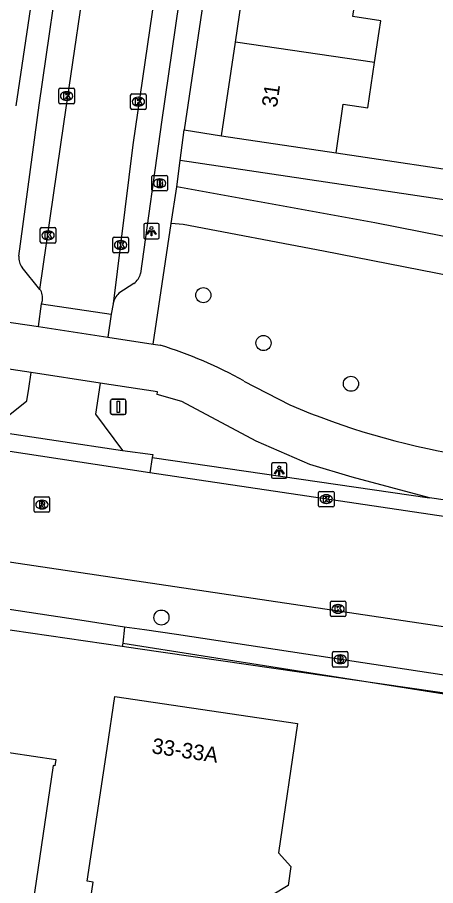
# Model space of a CAD drawing. Extents: x 163686 to 164493, y 382719 to 383870.
# Drawn here: x 164082.8 to 164109.8, y 382884.7 to 382940.9 of the extents above; entities that cross this region are included whole.
import ezdxf

# ---------------------------------------------------------------- set-up
doc = ezdxf.new("R2010")
doc.units = 0
for name, color, linetype in [('IMGEO_Boom', 7, 'Continuous'), ('IMGEO_Brandkraan', 7, 'Continuous'), ('IMGEO_Fietspad_gesloten', 7, 'Continuous'), ('IMGEO_Groenvoorziening', 7, 'Continuous'), ('IMGEO_Hek', 7, 'Continuous'), ('IMGEO_Kolk', 7, 'Continuous'), ('IMGEO_Lichtpunt', 7, 'Continuous'), ('IMGEO_Pand', 7, 'Continuous'), ('IMGEO_Pand_nummerreeks', 7, 'Continuous'), ('IMGEO_Rijbaan_lokaal_gesloten', 7, 'Continuous'), ('IMGEO_Rijbaan_lokaal_open', 7, 'Continuous'), ('IMGEO_Rioolput', 7, 'Continuous'), ('IMGEO_Verkeersbordpaal', 7, 'Continuous'), ('IMGEO_Voetpad_open', 7, 'Continuous')]:
    doc.layers.add(name, color=color, linetype=linetype)

msp = doc.modelspace()

# ---------------------------------------------------------------- linework, layer by layer
at = {"layer": 'IMGEO_Boom'}
for centre in [(164094.797, 382922.922), (164098.694, 382919.82), (164104.362, 382917.184), (164092.085, 382902.04)]:
    msp.add_circle(centre, 0.489, dxfattribs=at)
at = {"layer": 'IMGEO_Brandkraan'}
for p, q in [((164091.469, 382929.744), (164091.469, 382930.596)), ((164091.544, 382930.67), (164092.396, 382930.67)), ((164092.47, 382930.596), (164092.47, 382929.744)), ((164091.957, 382930.45), (164091.982, 382930.45)), ((164092.396, 382929.67), (164091.544, 382929.67)), ((164091.98, 382929.89), (164091.955, 382929.89)), ((164103.167, 382898.911), (164103.167, 382899.763)), ((164103.242, 382899.837), (164104.094, 382899.837)), ((164103.655, 382899.617), (164103.68, 382899.617)), ((164104.168, 382899.763), (164104.168, 382898.911)), ((164103.678, 382899.057), (164103.653, 382899.057)), ((164104.094, 382898.837), (164103.242, 382898.837))]:
    msp.add_line(p, q, dxfattribs=at)
for points in [[(164091.469, 382929.744), (164091.469, 382930.596)], [(164091.544, 382930.67), (164092.396, 382930.67)], [(164092.47, 382930.596), (164092.47, 382929.744)], [(164091.817, 382930.37), (164091.817, 382929.97), (164092.03, 382929.97)], [(164092.048, 382930.37), (164091.817, 382930.37)], [(164091.996, 382930.289), (164091.942, 382930.289), (164091.942, 382930.213)], [(164091.942, 382930.213), (164091.995, 382930.213)], [(164092.004, 382930.137), (164091.942, 382930.137), (164091.942, 382930.056)], [(164091.942, 382930.056), (164092.004, 382930.056)], [(164092.396, 382929.67), (164091.544, 382929.67)], [(164103.167, 382898.911), (164103.167, 382899.763)], [(164103.242, 382899.837), (164104.094, 382899.837)], [(164103.515, 382899.537), (164103.515, 382899.137), (164103.728, 382899.137)], [(164103.746, 382899.537), (164103.515, 382899.537)], [(164104.168, 382899.763), (164104.168, 382898.911)], [(164103.694, 382899.456), (164103.64, 382899.456), (164103.64, 382899.38)], [(164103.64, 382899.38), (164103.693, 382899.38)], [(164103.702, 382899.304), (164103.64, 382899.304), (164103.64, 382899.223)], [(164103.64, 382899.223), (164103.702, 382899.223)], [(164104.094, 382898.837), (164103.242, 382898.837)]]:
    msp.add_lwpolyline(points, dxfattribs=at)
for centre, radius, start, end in [((164091.546, 382930.594), 0.0765, 91.552, 178.448), ((164091.546, 382930.594), 0.0765, 91.552, 178.448), ((164092.394, 382930.594), 0.0765, 1.552, 88.448), ((164092.394, 382930.594), 0.0765, 1.552, 88.448), ((164091.997, 382930.251), 0.0379, 267.8285, 90.9355), ((164092.005, 382930.096), 0.0404, 269.8759, 90.5077), ((164092.036, 382930.221), 0.251, 268.6676, 293.5347), ((164092.052, 382930.225), 0.145, 59.4692, 91.5367), ((164092.077, 382930.272), 0.0922, 285.5137, 58.1501), ((164092.082, 382930.08), 0.105, 301.3115, 78.989), ((164091.546, 382929.746), 0.0765, 181.552, 268.448), ((164091.546, 382929.746), 0.0765, 181.552, 268.448), ((164092.394, 382929.746), 0.0765, 271.552, 358.448), ((164092.394, 382929.746), 0.0765, 271.552, 358.448), ((164103.244, 382899.761), 0.0765, 91.552, 178.448), ((164103.244, 382899.761), 0.0765, 91.552, 178.448), ((164103.75, 382899.392), 0.145, 59.4692, 91.5367), ((164104.092, 382899.761), 0.0765, 1.552, 88.448), ((164104.092, 382899.761), 0.0765, 1.552, 88.448), ((164103.695, 382899.418), 0.0379, 267.8285, 90.9355), ((164103.703, 382899.263), 0.0404, 269.8759, 90.5077), ((164103.734, 382899.388), 0.251, 268.6676, 293.5347), ((164103.775, 382899.439), 0.0922, 285.5137, 58.1501), ((164103.78, 382899.247), 0.105, 301.3115, 78.989), ((164103.244, 382898.913), 0.0765, 181.552, 268.448), ((164103.244, 382898.913), 0.0765, 181.552, 268.448), ((164104.092, 382898.913), 0.0765, 271.552, 358.448), ((164104.092, 382898.913), 0.0765, 271.552, 358.448)]:
    msp.add_arc(centre, radius, start, end, dxfattribs=at)
for centre, major_axis, ratio, start_param, end_param in [((164091.956, 382930.17), (-0.387, 0.002), 0.722429, 4.712389, 7.853982), ((164091.981, 382930.17), (-0.39, 0.002), 0.717154, 1.570796, 4.712389), ((164103.654, 382899.337), (-0.387, 0.002), 0.722429, 4.712389, 7.853982), ((164103.679, 382899.337), (-0.39, 0.002), 0.717154, 1.570796, 4.712389)]:
    msp.add_ellipse(centre, major_axis=major_axis, ratio=ratio, start_param=start_param, end_param=end_param, dxfattribs=at)
at = {"layer": 'IMGEO_Fietspad_gesloten'}
for points in [[(164080.709, 382921.39), (164084.114, 382920.888)], [(164088.61, 382920.207), (164091.557, 382919.741)], [(164091.557, 382919.741), (164092.007, 382919.674)], [(164083.648, 382917.908), (164080.015, 382918.445), (164079.969, 382918.239)], [(164109.452, 382909.801), (164104.433, 382911.123), (164101.705, 382911.946), (164098.222, 382913.466), (164093.404, 382916.027), (164091.798, 382916.497), (164091.819, 382916.666), (164088.11, 382917.218)], [(164097.423, 382917.361), (164100.411, 382915.813)], [(164122.324, 382907.915), (164109.452, 382909.801)]]:
    msp.add_lwpolyline(points, dxfattribs=at)
for centre, radius, start, end in [((164084.043, 382893.528), 27.333, 60.6896, 73.0589), ((164119.389, 382960.225), 48.297, 246.8617, 260.5241)]:
    msp.add_arc(centre, radius, start, end, dxfattribs=at)
at = {"layer": 'IMGEO_Groenvoorziening'}
for points in [[(164093.559, 382933.622), (164095.981, 382933.235)], [(164139.939, 382924.7), (164093.297, 382931.638)], [(164103.402, 382932.145), (164113.229, 382930.665)]]:
    msp.add_lwpolyline(points, dxfattribs=at)
at = {"layer": 'IMGEO_Hek'}
msp.add_lwpolyline([(164089.574, 382900.373), (164110.403, 382897.109), (164139.681, 382892.918)], dxfattribs=at)
at = {"layer": 'IMGEO_Kolk'}
for p, q in [((164085.442, 382935.392), (164085.442, 382936.244)), ((164085.517, 382936.318), (164086.369, 382936.318)), ((164085.93, 382936.098), (164085.955, 382936.098)), ((164086.443, 382936.244), (164086.443, 382935.392)), ((164085.953, 382935.538), (164085.928, 382935.538)), ((164090.09, 382935.03), (164090.09, 382935.882)), ((164090.165, 382935.956), (164091.017, 382935.956)), ((164090.578, 382935.736), (164090.603, 382935.736)), ((164091.091, 382935.882), (164091.091, 382935.03)), ((164086.369, 382935.318), (164085.517, 382935.318)), ((164090.601, 382935.176), (164090.576, 382935.176)), ((164091.017, 382934.956), (164090.165, 382934.956)), ((164084.238, 382926.368), (164084.238, 382927.22)), ((164084.313, 382927.294), (164085.165, 382927.294)), ((164085.239, 382927.22), (164085.239, 382926.368)), ((164084.726, 382927.074), (164084.751, 382927.074)), ((164088.941, 382925.747), (164088.941, 382926.599)), ((164089.016, 382926.673), (164089.868, 382926.673)), ((164089.942, 382926.599), (164089.942, 382925.747)), ((164085.165, 382926.294), (164084.313, 382926.294)), ((164084.749, 382926.514), (164084.724, 382926.514)), ((164089.429, 382926.453), (164089.454, 382926.453)), ((164089.868, 382925.673), (164089.016, 382925.673)), ((164089.452, 382925.893), (164089.427, 382925.893)), ((164102.265, 382909.284), (164102.265, 382910.136)), ((164102.34, 382910.21), (164103.192, 382910.21)), ((164102.753, 382909.99), (164102.778, 382909.99)), ((164103.266, 382910.136), (164103.266, 382909.284)), ((164103.192, 382909.21), (164102.34, 382909.21)), ((164102.776, 382909.43), (164102.751, 382909.43)), ((164103.027, 382902.175), (164103.027, 382903.027)), ((164103.102, 382903.101), (164103.954, 382903.101)), ((164104.028, 382903.027), (164104.028, 382902.175)), ((164103.515, 382902.881), (164103.54, 382902.881)), ((164103.954, 382902.101), (164103.102, 382902.101)), ((164103.538, 382902.321), (164103.513, 382902.321))]:
    msp.add_line(p, q, dxfattribs=at)
for points in [[(164085.442, 382935.392), (164085.442, 382936.244)], [(164085.517, 382936.318), (164086.369, 382936.318)], [(164086.443, 382936.244), (164086.443, 382935.392)], [(164085.763, 382936.018), (164085.886, 382936.018), (164085.886, 382935.867), (164086.016, 382936.018), (164086.18, 382936.018), (164086.034, 382935.867), (164086.187, 382935.618), (164086.035, 382935.618), (164085.95, 382935.782), (164085.886, 382935.715), (164085.886, 382935.618), (164085.763, 382935.618), (164085.763, 382936.018)], [(164090.09, 382935.03), (164090.09, 382935.882)], [(164090.165, 382935.956), (164091.017, 382935.956)], [(164090.411, 382935.656), (164090.534, 382935.656), (164090.534, 382935.505), (164090.664, 382935.656), (164090.828, 382935.656), (164090.682, 382935.505), (164090.835, 382935.256), (164090.683, 382935.256), (164090.598, 382935.42), (164090.534, 382935.353), (164090.534, 382935.256), (164090.411, 382935.256), (164090.411, 382935.656)], [(164091.091, 382935.882), (164091.091, 382935.03)], [(164086.369, 382935.318), (164085.517, 382935.318)], [(164091.017, 382934.956), (164090.165, 382934.956)], [(164084.238, 382926.368), (164084.238, 382927.22)], [(164084.313, 382927.294), (164085.165, 382927.294)], [(164085.239, 382927.22), (164085.239, 382926.368)], [(164084.559, 382926.994), (164084.682, 382926.994), (164084.682, 382926.843), (164084.812, 382926.994), (164084.976, 382926.994), (164084.83, 382926.843), (164084.983, 382926.594), (164084.831, 382926.594), (164084.746, 382926.758), (164084.682, 382926.691), (164084.682, 382926.594), (164084.559, 382926.594), (164084.559, 382926.994)], [(164088.941, 382925.747), (164088.941, 382926.599)], [(164089.016, 382926.673), (164089.868, 382926.673)], [(164089.942, 382926.599), (164089.942, 382925.747)], [(164085.165, 382926.294), (164084.313, 382926.294)], [(164089.262, 382926.373), (164089.385, 382926.373), (164089.385, 382926.222), (164089.515, 382926.373), (164089.679, 382926.373), (164089.533, 382926.222), (164089.686, 382925.973), (164089.534, 382925.973), (164089.449, 382926.137), (164089.385, 382926.07), (164089.385, 382925.973), (164089.262, 382925.973), (164089.262, 382926.373)], [(164089.868, 382925.673), (164089.016, 382925.673)], [(164102.265, 382909.284), (164102.265, 382910.136)], [(164102.34, 382910.21), (164103.192, 382910.21)], [(164102.586, 382909.91), (164102.709, 382909.91), (164102.709, 382909.759), (164102.839, 382909.91), (164103.003, 382909.91), (164102.857, 382909.759), (164103.01, 382909.51), (164102.858, 382909.51), (164102.773, 382909.674), (164102.709, 382909.607), (164102.709, 382909.51), (164102.586, 382909.51), (164102.586, 382909.91)], [(164103.266, 382910.136), (164103.266, 382909.284)], [(164103.192, 382909.21), (164102.34, 382909.21)], [(164103.027, 382902.175), (164103.027, 382903.027)], [(164103.102, 382903.101), (164103.954, 382903.101)], [(164104.028, 382903.027), (164104.028, 382902.175)], [(164103.348, 382902.801), (164103.471, 382902.801), (164103.471, 382902.65), (164103.601, 382902.801), (164103.765, 382902.801), (164103.619, 382902.65), (164103.772, 382902.401), (164103.62, 382902.401), (164103.535, 382902.565), (164103.471, 382902.498), (164103.471, 382902.401), (164103.348, 382902.401), (164103.348, 382902.801)], [(164103.954, 382902.101), (164103.102, 382902.101)]]:
    msp.add_lwpolyline(points, dxfattribs=at)
for centre, start, end in [((164085.519, 382936.242), 91.552, 178.448), ((164085.519, 382936.242), 91.552, 178.448), ((164086.367, 382936.242), 1.552, 88.448), ((164086.367, 382936.242), 1.552, 88.448), ((164090.167, 382935.88), 91.552, 178.448), ((164090.167, 382935.88), 91.552, 178.448), ((164091.015, 382935.88), 1.552, 88.448), ((164091.015, 382935.88), 1.552, 88.448), ((164085.519, 382935.394), 181.552, 268.448), ((164085.519, 382935.394), 181.552, 268.448), ((164086.367, 382935.394), 271.552, 358.448), ((164086.367, 382935.394), 271.552, 358.448), ((164090.167, 382935.032), 181.552, 268.448), ((164090.167, 382935.032), 181.552, 268.448), ((164091.015, 382935.032), 271.552, 358.448), ((164091.015, 382935.032), 271.552, 358.448), ((164084.315, 382927.218), 91.552, 178.448), ((164084.315, 382927.218), 91.552, 178.448), ((164085.163, 382927.218), 1.552, 88.448), ((164085.163, 382927.218), 1.552, 88.448), ((164089.018, 382926.597), 91.552, 178.448), ((164089.018, 382926.597), 91.552, 178.448), ((164089.866, 382926.597), 1.552, 88.448), ((164089.866, 382926.597), 1.552, 88.448), ((164084.315, 382926.37), 181.552, 268.448), ((164084.315, 382926.37), 181.552, 268.448), ((164085.163, 382926.37), 271.552, 358.448), ((164085.163, 382926.37), 271.552, 358.448), ((164089.018, 382925.749), 181.552, 268.448), ((164089.018, 382925.749), 181.552, 268.448), ((164089.866, 382925.749), 271.552, 358.448), ((164089.866, 382925.749), 271.552, 358.448), ((164102.342, 382910.134), 91.552, 178.448), ((164102.342, 382910.134), 91.552, 178.448), ((164103.19, 382910.134), 1.552, 88.448), ((164103.19, 382910.134), 1.552, 88.448), ((164102.342, 382909.286), 181.552, 268.448), ((164102.342, 382909.286), 181.552, 268.448), ((164103.19, 382909.286), 271.552, 358.448), ((164103.19, 382909.286), 271.552, 358.448), ((164103.104, 382903.025), 91.552, 178.448), ((164103.104, 382903.025), 91.552, 178.448), ((164103.952, 382903.025), 1.552, 88.448), ((164103.952, 382903.025), 1.552, 88.448), ((164103.104, 382902.177), 181.552, 268.448), ((164103.104, 382902.177), 181.552, 268.448), ((164103.952, 382902.177), 271.552, 358.448), ((164103.952, 382902.177), 271.552, 358.448)]:
    msp.add_arc(centre, 0.0765, start, end, dxfattribs=at)
for centre, major_axis, ratio, start_param, end_param in [((164085.929, 382935.818), (-0.387, 0.002), 0.722429, 4.712389, 7.853982), ((164085.954, 382935.818), (-0.39, 0.002), 0.717154, 1.570796, 4.712389), ((164090.577, 382935.456), (-0.387, 0.002), 0.722429, 4.712389, 7.853982), ((164090.602, 382935.456), (-0.39, 0.002), 0.717154, 1.570796, 4.712389), ((164084.725, 382926.794), (-0.387, 0.002), 0.722429, 4.712389, 7.853982), ((164084.75, 382926.794), (-0.39, 0.002), 0.717154, 1.570796, 4.712389), ((164089.428, 382926.173), (-0.387, 0.002), 0.722429, 4.712389, 7.853982), ((164089.453, 382926.173), (-0.39, 0.002), 0.717154, 1.570796, 4.712389), ((164102.752, 382909.71), (-0.387, 0.002), 0.722429, 4.712389, 7.853982), ((164102.777, 382909.71), (-0.39, 0.002), 0.717154, 1.570796, 4.712389), ((164103.514, 382902.601), (-0.387, 0.002), 0.722429, 4.712389, 7.853982), ((164103.539, 382902.601), (-0.39, 0.002), 0.717154, 1.570796, 4.712389)]:
    msp.add_ellipse(centre, major_axis=major_axis, ratio=ratio, start_param=start_param, end_param=end_param, dxfattribs=at)
at = {"layer": 'IMGEO_Lichtpunt'}
for p, q in [((164090.939, 382927.468), (164090.939, 382926.661)), ((164090.939, 382927.468), (164090.939, 382926.661)), ((164091.841, 382927.563), (164091.033, 382927.563)), ((164091.841, 382927.563), (164091.033, 382927.563)), ((164091.935, 382926.661), (164091.935, 382927.468)), ((164091.935, 382926.661), (164091.935, 382927.468)), ((164091.033, 382926.567), (164091.841, 382926.567)), ((164091.033, 382926.567), (164091.841, 382926.567)), ((164099.216, 382911.962), (164099.216, 382911.155)), ((164099.216, 382911.962), (164099.216, 382911.155)), ((164100.118, 382912.057), (164099.31, 382912.057)), ((164100.118, 382912.057), (164099.31, 382912.057)), ((164100.212, 382911.155), (164100.212, 382911.962)), ((164100.212, 382911.155), (164100.212, 382911.962)), ((164099.31, 382911.061), (164100.118, 382911.061)), ((164099.31, 382911.061), (164100.118, 382911.061))]:
    msp.add_line(p, q, dxfattribs=at)
for points in [[(164091.313, 382927.132), (164091.352, 382927.104), (164091.164, 382926.842), (164091.126, 382926.869), (164091.313, 382927.132)], [(164091.525, 382927.104), (164091.563, 382927.131), (164091.75, 382926.869), (164091.711, 382926.841), (164091.525, 382927.104)], [(164091.415, 382927.084), (164091.462, 382927.084), (164091.462, 382926.762), (164091.415, 382926.762), (164091.415, 382927.084)], [(164099.59, 382911.626), (164099.629, 382911.598), (164099.441, 382911.336), (164099.403, 382911.363), (164099.59, 382911.626)], [(164099.692, 382911.578), (164099.739, 382911.578), (164099.739, 382911.256), (164099.692, 382911.256), (164099.692, 382911.578)], [(164099.802, 382911.598), (164099.84, 382911.625), (164100.027, 382911.363), (164099.988, 382911.335), (164099.802, 382911.598)]]:
    msp.add_lwpolyline(points, dxfattribs=at)
for centre in [(164091.438, 382927.266), (164099.715, 382911.76)]:
    msp.add_circle(centre, 0.0994, dxfattribs=at)
for centre, start, end in [((164091.033, 382927.468), 90, 180), ((164091.033, 382927.468), 90, 180), ((164091.841, 382927.468), 0, 90), ((164091.841, 382927.468), 0, 90), ((164091.033, 382926.661), 180, 270), ((164091.033, 382926.661), 180, 270), ((164091.841, 382926.661), 270, 0), ((164091.841, 382926.661), 270, 360), ((164099.31, 382911.962), 90, 180), ((164099.31, 382911.962), 90, 180), ((164100.118, 382911.962), 0, 90), ((164100.118, 382911.962), 0, 90), ((164099.31, 382911.155), 180, 270), ((164099.31, 382911.155), 180, 270), ((164100.118, 382911.155), 270, 0), ((164100.118, 382911.155), 270, 360)]:
    msp.add_arc(centre, 0.0946, start, end, dxfattribs=at)
at = {"layer": 'IMGEO_Pand'}
for points in [[(164096.872, 382939.305), (164097.742, 382945.228)], [(164105.883, 382937.98), (164106.184, 382939.997), (164106.288, 382940.698), (164104.484, 382940.966), (164104.954, 382944.169)], [(164095.981, 382933.235), (164096.872, 382939.305)], [(164105.883, 382937.98), (164096.872, 382939.305)], [(164103.402, 382932.145), (164103.863, 382935.283), (164105.446, 382935.051), (164105.883, 382937.98)], [(164095.981, 382933.235), (164103.402, 382932.145)], [(164045.234, 382877.827), (164046.187, 382883.846), (164046.041, 382883.87), (164048.336, 382898.347), (164061.914, 382896.34), (164063.498, 382896.105), (164063.459, 382895.814), (164065.07, 382895.583), (164071.442, 382896.029), (164071.431, 382896.326), (164072.411, 382896.362), (164072.195, 382894.782), (164085.244, 382892.851), (164085.183, 382892.441), (164085.07, 382892.457), (164082.112, 382872.347), (164045.234, 382877.827)], [(164085.914, 382873.172), (164087.652, 382884.904), (164087.276, 382884.978), (164088.323, 382891.981), (164088.56, 382893.566), (164089.062, 382896.926), (164100.898, 382895.171), (164099.669, 382886.81), (164100.463, 382885.922), (164100.285, 382884.683), (164099.261, 382884.054), (164099.161, 382883.418), (164107.104, 382882.257), (164106.377, 382877.311), (164105.346, 382870.296), (164085.914, 382873.172)]]:
    msp.add_lwpolyline(points, dxfattribs=at)
at = {"layer": 'IMGEO_Rijbaan_lokaal_gesloten'}
for points in [[(164166.332, 382893.113), (164033.326, 382912.894), (164021.113, 382914.698), (163965.93, 382922.852)], [(164091.335, 382911.423), (164079.7, 382913.184)], [(164136.237, 382904.741), (164091.335, 382911.423)]]:
    msp.add_lwpolyline(points, dxfattribs=at)
at = {"layer": 'IMGEO_Rijbaan_lokaal_open'}
for points in [[(164084.208, 382923.296), (164085.76, 382934.012), (164091.005, 382969.792)], [(164095.535, 382969.127), (164090.231, 382932.66), (164088.947, 382922.357)], [(164084.114, 382920.888), (164084.307, 382922.351)], [(164084.307, 382922.351), (164084.375, 382922.567)], [(164084.307, 382922.351), (164088.832, 382921.684)], [(164088.947, 382922.357), (164088.832, 382921.684)], [(164088.832, 382921.684), (164088.61, 382920.207)], [(164084.114, 382920.888), (164088.61, 382920.207)], [(164080.954, 382914.16), (164083.365, 382916.067), (164083.489, 382916.871), (164083.648, 382917.908)], [(164088.11, 382917.218), (164083.648, 382917.908)], [(164088.11, 382917.218), (164087.808, 382915.203), (164089.553, 382912.871)], [(164080.954, 382914.16), (164089.553, 382912.871)]]:
    msp.add_lwpolyline(points, dxfattribs=at)
msp.add_arc((164083.438, 382922.736), 0.952, 349.7711, 36.0344, dxfattribs=at)
at = {"layer": 'IMGEO_Rioolput'}
for p, q in [((164083.84, 382908.932), (164083.84, 382909.784)), ((164083.915, 382909.858), (164084.767, 382909.858)), ((164084.841, 382909.784), (164084.841, 382908.932)), ((164084.328, 382909.638), (164084.353, 382909.638)), ((164084.767, 382908.858), (164083.915, 382908.858)), ((164084.351, 382909.078), (164084.326, 382909.078))]:
    msp.add_line(p, q, dxfattribs=at)
for points in [[(164083.84, 382908.932), (164083.84, 382909.784)], [(164083.915, 382909.858), (164084.767, 382909.858)], [(164084.841, 382909.784), (164084.841, 382908.932)], [(164084.429, 382909.556), (164084.177, 382909.558), (164084.177, 382909.158)], [(164084.177, 382909.158), (164084.301, 382909.158), (164084.301, 382909.32), (164084.312, 382909.32)], [(164084.355, 382909.477), (164084.301, 382909.477), (164084.301, 382909.396)], [(164084.301, 382909.396), (164084.353, 382909.396)], [(164084.359, 382909.291), (164084.43, 382909.158), (164084.57, 382909.158), (164084.505, 382909.284)], [(164084.767, 382908.858), (164083.915, 382908.858)]]:
    msp.add_lwpolyline(points, dxfattribs=at)
for centre, radius, start, end in [((164083.917, 382909.782), 0.0765, 91.552, 178.448), ((164083.917, 382909.782), 0.0765, 91.552, 178.448), ((164084.765, 382909.782), 0.0765, 1.552, 88.448), ((164084.765, 382909.782), 0.0765, 1.552, 88.448), ((164084.311, 382909.267), 0.0533, 26.0293, 88.6989), ((164084.337, 382909.585), 0.19, 274.7715, 282.9687), ((164084.361, 382909.381), 0.0964, 77.0061, 93.1865), ((164084.375, 382909.438), 0.0378, 276.6634, 79.6772), ((164084.428, 382909.446), 0.109, 350.3612, 89.416), ((164084.426, 382909.446), 0.112, 277.5842, 350.9817), ((164084.41, 382909.231), 0.108, 29.5134, 73.7905), ((164083.917, 382908.934), 0.0765, 181.552, 268.448), ((164083.917, 382908.934), 0.0765, 181.552, 268.448), ((164084.765, 382908.934), 0.0765, 271.552, 358.448), ((164084.765, 382908.934), 0.0765, 271.552, 358.448)]:
    msp.add_arc(centre, radius, start, end, dxfattribs=at)
for centre, major_axis, ratio, start_param, end_param in [((164084.327, 382909.358), (-0.387, 0.002), 0.722429, 4.712389, 7.853982), ((164084.352, 382909.358), (-0.39, 0.002), 0.717154, 1.570796, 4.712389)]:
    msp.add_ellipse(centre, major_axis=major_axis, ratio=ratio, start_param=start_param, end_param=end_param, dxfattribs=at)
at = {"layer": 'IMGEO_Verkeersbordpaal'}
for p, q in [((164088.79, 382915.286), (164088.79, 382916.086)), ((164088.79, 382916.086), (164088.79, 382915.286)), ((164088.89, 382916.186), (164089.68, 382916.186)), ((164089.68, 382916.186), (164088.89, 382916.186)), ((164089.78, 382916.086), (164089.78, 382915.286)), ((164089.78, 382915.286), (164089.78, 382916.086)), ((164089.68, 382915.186), (164088.89, 382915.186)), ((164088.89, 382915.186), (164089.68, 382915.186))]:
    msp.add_line(p, q, dxfattribs=at)
msp.add_lwpolyline([(164089.21, 382916.061), (164089.36, 382916.061), (164089.36, 382915.311), (164089.21, 382915.311), (164089.21, 382916.061)], dxfattribs=at)
for centre, start, end in [((164088.89, 382916.086), 90, 180), ((164088.89, 382916.086), 90, 180), ((164089.68, 382916.086), 0, 90), ((164089.68, 382916.086), 360, 90), ((164088.89, 382915.286), 180, 270), ((164088.89, 382915.286), 180, 270), ((164089.68, 382915.286), 270, 0), ((164089.68, 382915.286), 270, 0)]:
    msp.add_arc(centre, 0.1, start, end, dxfattribs=at)
at = {"layer": 'IMGEO_Voetpad_open'}
for points in [[(164082.663, 382935.187), (164087.983, 382970.912)], [(164095.638, 382969.83), (164096.113, 382968.492), (164096.624, 382967.579), (164096.805, 382966.64), (164092.086, 382934.118), (164090.732, 382924.32)], [(164098.876, 382969.417), (164093.559, 382933.622)], [(164082.844, 382925.441), (164084.171, 382935.233), (164088.903, 382967.882)], [(164093.297, 382931.638), (164093.559, 382933.622)], [(164093.072, 382929.933), (164093.297, 382931.638)], [(164092.722, 382927.559), (164093.072, 382929.933)], [(164138.954, 382920.045), (164136.589, 382920.625), (164116.325, 382925.558), (164105.912, 382927.595), (164094.036, 382929.771), (164093.072, 382929.933)], [(164091.557, 382919.741), (164092.722, 382927.559)], [(164138.554, 382917.653), (164135.761, 382918.443), (164115.146, 382923.304), (164102.583, 382925.772), (164093.486, 382927.494), (164092.722, 382927.559)], [(164084.208, 382923.296), (164083.06, 382924.712)], [(164090.306, 382923.674), (164089.32, 382923.041)], [(164089.553, 382912.871), (164091.518, 382912.593), (164091.493, 382912.402)], [(164091.493, 382912.402), (164091.335, 382911.423)], [(164091.493, 382912.402), (164109.452, 382909.801)], [(164089.694, 382901.426), (164086.798, 382901.866), (164080.21, 382902.866)], [(164089.551, 382900.168), (164080.011, 382901.545)], [(164089.694, 382901.426), (164089.574, 382900.373), (164089.551, 382900.168)], [(164110.539, 382898.278), (164093.052, 382900.94), (164090.994, 382901.238), (164089.694, 382901.426)], [(164139.681, 382892.918), (164090.548, 382900.024), (164089.551, 382900.168)]]:
    msp.add_lwpolyline(points, dxfattribs=at)
for centre, radius, start, end in [((164083.838, 382925.339), 0.999, 174.1429, 218.8658), ((164089.501, 382924.668), 1.279, 308.9941, 344.2008), ((164090.244, 382922.093), 1.324, 134.2799, 168.5109)]:
    msp.add_arc(centre, radius, start, end, dxfattribs=at)

# ---------------------------------------------------------------- texts
at = {"layer": 'IMGEO_Pand_nummerreeks'}
for s, rotation, p in [('31', 81.647, (164099.562, 382935.039)), ('33-33A', 351.5654, (164091.415, 382893.261))]:
    msp.add_text(s, height=1, rotation=rotation, dxfattribs=at).set_placement(p)

doc.saveas('drawing.dxf')
